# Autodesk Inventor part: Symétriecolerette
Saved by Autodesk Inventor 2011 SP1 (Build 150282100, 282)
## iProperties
Created: 2010-12
Part Number: Symétriecolerette
Document SubType Name: Modeling
Designer: eric
Density: 1 g/cm^3
Author: eric
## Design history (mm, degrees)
feature "Base1"
node "Solide1"
node "Corps solides"
node "Corps surfaciques"
